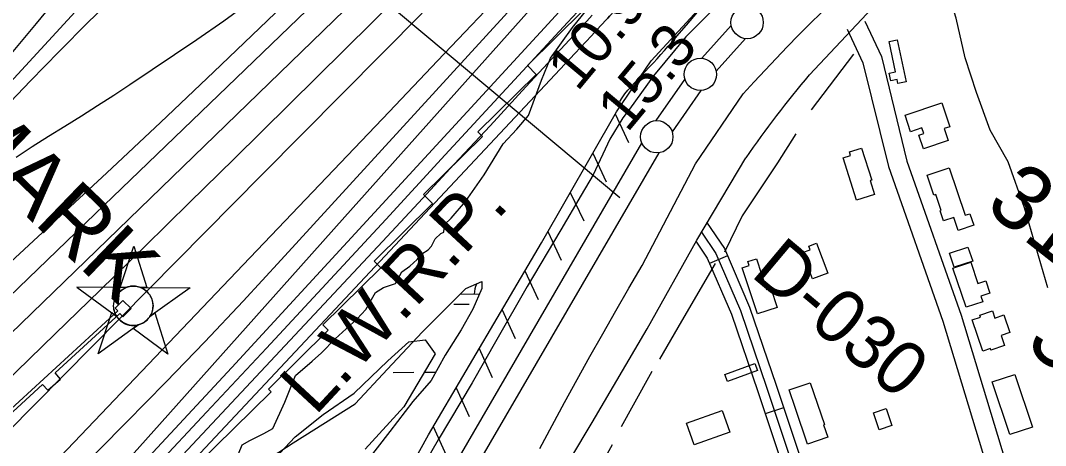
# Model space of a CAD drawing. Extents: x 3598634 to 3636690, y 517270 to 542944.
# Drawn here: x 3604825 to 3606411, y 525564 to 526222 of the extents above; entities that cross this region are included whole.
import ezdxf

# ---------------------------------------------------------------- set-up
doc = ezdxf.new("R2010")
doc.units = 0
for name, color, linetype in [('V-BLDG-OTLN', 7, 'Continuous'), ('V-CHAN-DOCK', 7, 'Continuous'), ('V-CHAN-NAID', 7, 'Continuous'), ('V-LEVE-TOET', 7, 'Continuous'), ('V-RIVR-EDGE', 7, 'Continuous'), ('V-RIVR-RANG', 7, 'Continuous'), ('V-RIVR-RANG-IDEN', 7, 'Continuous'), ('V-ROAD-CNTR', 7, 'Continuous'), ('V-RRAP-FSHR', 7, 'Continuous'), ('V-RRAP-RVMT', 7, 'Continuous'), ('V-SITE-VEGE', 7, 'Continuous'), ('V-SURV-IDEN', 7, 'Continuous'), ('V-SURV-LINE', 7, 'Continuous'), ('V-TOPO-DPTH', 7, 'Continuous'), ('V-TOPO-MAJR', 7, 'Continuous'), ('V-TOPO-MINR', 7, 'Continuous'), ('V-TOPO-SHOR', 7, 'Continuous'), ('V-TOPO-WATR', 7, 'Continuous'), ('V-TOPO-WATR-IDEN', 7, 'Continuous'), ('V-WETL-SWMP', 7, 'Continuous')]:
    doc.layers.add(name, color=color, linetype=linetype)

msp = doc.modelspace()

# ---------------------------------------------------------------- linework, layer by layer
at = {"layer": 'V-BLDG-OTLN'}
for points in [[(3606181.2, 526192), (3606195.4, 526126.8), (3606182.7, 526124), (3606181.3, 526130.3), (3606171.5, 526128.1), (3606168.9, 526140.2), (3606179, 526142.4), (3606168.8, 526189.3)], [(3606193.8, 526075.1), (3606250.7, 526094), (3606262.8, 526057.3), (3606254.4, 526054.5), (3606260.6, 526035.8), (3606222, 526023), (3606215, 526044.1), (3606222.6, 526046.7), (3606219.7, 526055.3), (3606202.3, 526049.5)], [(3606107.5, 526018.2), (3606126.1, 526024.2), (3606142, 525974.7), (3606139.6, 525973.9), (3606146.5, 525952.5), (3606118.7, 525943.7), (3606097.7, 526009.2), (3606109.2, 526012.9)], [(3606261.9, 525993.9), (3606286.8, 525920.3), (3606294, 525922.7), (3606300, 525904.8), (3606275.6, 525896.6), (3606268.9, 525916.7), (3606253.2, 525911.4), (3606248, 525926.9), (3606249.6, 525927.4), (3606241.2, 525952.3), (3606238.1, 525951.3), (3606227.7, 525982.4)], [(3606056.7, 525877), (3606074.2, 525830.8), (3606050.2, 525821.7), (3606034.8, 525862.4), (3606046.5, 525866.8), (3606044.5, 525872.3)], [(3606262.4, 525861.5), (3606291, 525871.1), (3606298.3, 525849.4), (3606269.7, 525839.8)], [(3605965.1, 525767.5), (3605941.6, 525838.8), (3605952.2, 525842.3), (3605950.2, 525848.6), (3605963.6, 525853), (3605979.2, 525805.5), (3605985.7, 525807.6), (3605995.6, 525777.5)], [(3606288.1, 525777.9), (3606267.8, 525838.5), (3606295.5, 525847.7), (3606306.5, 525814.8), (3606318.4, 525818.8), (3606324.8, 525799.8), (3606311, 525795.1), (3606313.9, 525786.5)], [(3606313.9, 525709.9), (3606297.3, 525758.3), (3606310.3, 525762.7), (3606309.3, 525765.7), (3606328.9, 525772.4), (3606332.7, 525761.1), (3606346.7, 525765.9), (3606356, 525738.7), (3606342.3, 525734), (3606347.5, 525718.7), (3606326.5, 525711.6), (3606325.7, 525713.9)], [(3605914.9, 525673.7), (3605961.1, 525690.7), (3605965.1, 525679.9), (3605918.6, 525663)], [(3606363.5, 525673.8), (3606390.7, 525592.3), (3606355.9, 525580.7), (3606328.7, 525662.2)], [(3606014.4, 525650), (3606047, 525661.1), (3606068.9, 525596.6), (3606067.6, 525596.1), (3606074.2, 525576.8), (3606042.5, 525566), (3606023.8, 525621.2), (3606024.1, 525621.3)], [(3605922.5, 525584.8), (3605867.1, 525565), (3605855.2, 525598.3), (3605910.6, 525618.1)], [(3606164.6, 525621.1), (3606173.4, 525595), (3606153.7, 525588.4), (3606145, 525614.5)]]:
    msp.add_lwpolyline(points, close=True, dxfattribs=at)
at = {"layer": 'V-CHAN-DOCK'}
msp.add_lwpolyline([(3604778.3, 525563.9), (3604766.7, 525574.4), (3604858.4, 525658.5), (3604866.7, 525649.7), (3604886.5, 525666.4), (3604878.2, 525676.6), (3604978.3, 525768.3), (3604983, 525762.9), (3604995.7, 525775.9), (3604982.7, 525788.5), (3604971.2, 525776.7), (3604975.1, 525772.1), (3604688.2, 525509.3)], dxfattribs=at)
at = {"layer": 'V-CHAN-NAID'}
for points in [[(3604988.3, 525808.6), (3604978.7, 525808.7), (3604999.8, 525872.2), (3605020.1, 525808.4), (3605010.5, 525808.5), (3605008.9, 525809.1), (3605006.8, 525809.7), (3605004.8, 525810.1), (3605002.7, 525810.4), (3605001.6, 525810.5), (3605000, 525810.6), (3604998.3, 525810.6), (3604996.9, 525810.6), (3604995, 525810.4), (3604993.7, 525810.1), (3604991.9, 525809.7), (3604990.4, 525809.3), (3604989.3, 525809)], [(3604988.3, 525808.6), (3604911.8, 525809.2), (3604973.4, 525763.8), (3604972.3, 525765.7), (3604971.5, 525767.3), (3604970.6, 525769.3), (3604969.9, 525771.3), (3604969.6, 525772.7), (3604969.2, 525774.3), (3604969, 525775.7), (3604968.8, 525777.3), (3604968.7, 525779.1), (3604968.7, 525780.6), (3604968.8, 525782.7), (3604968.9, 525784.3), (3604969.3, 525786.5), (3604969.8, 525788.5), (3604970.4, 525790.3), (3604971.1, 525792), (3604971.8, 525793.6), (3604972.6, 525795.1), (3604973.7, 525796.9), (3604974.7, 525798.4), (3604975.7, 525799.6), (3604976.7, 525800.8), (3604978, 525802.1), (3604979.1, 525803.1), (3604980.8, 525804.5), (3604982, 525805.3), (3604983.7, 525806.4), (3604985.4, 525807.4), (3604986.9, 525808)], [(3605010.5, 525808.5), (3605087, 525807.9), (3605024.8, 525763.4), (3605025.7, 525764.9), (3605026.7, 525766.7), (3605027.4, 525768.3), (3605028.1, 525770.3), (3605028.7, 525772.1), (3605029.1, 525773.7), (3605029.4, 525775.7), (3605029.6, 525777.3), (3605029.7, 525779.5), (3605029.7, 525781.6), (3605029.5, 525783.8), (3605029.2, 525785.5), (3605028.7, 525787.8), (3605028.1, 525789.9), (3605027.4, 525791.9), (3605026.7, 525793.3), (3605025.7, 525795.2), (3605024.6, 525797), (3605023.4, 525798.7), (3605022.2, 525800.2), (3605020.9, 525801.6), (3605019.3, 525803.1), (3605017.5, 525804.5), (3605015.8, 525805.7), (3605014, 525806.8), (3605012.5, 525807.6)], [(3605006.7, 525750.5), (3604944.5, 525706), (3604965.7, 525769.5), (3604973.4, 525763.8), (3604974, 525762.8), (3604975.4, 525760.9), (3604976.6, 525759.5), (3604978.1, 525758), (3604979.5, 525756.8), (3604980.9, 525755.6), (3604982.3, 525754.6), (3604984, 525753.6), (3604985.7, 525752.7), (3604987.5, 525751.9), (3604988.9, 525751.3), (3604990.6, 525750.8), (3604992.8, 525750.2), (3604994.3, 525749.9), (3604996.4, 525749.7), (3604997.9, 525749.6), (3604999.8, 525749.6), (3605001.4, 525749.6), (3605003.2, 525749.8), (3605005.1, 525750.1)], [(3605024.8, 525763.4), (3605032.6, 525769), (3605052.8, 525705.2), (3604998.9, 525744.9), (3605006.7, 525750.5), (3605008.4, 525751), (3605010, 525751.5), (3605012.2, 525752.5), (3605013.9, 525753.3), (3605015.8, 525754.4), (3605017.5, 525755.7), (3605019.1, 525756.9), (3605020.4, 525758.1), (3605021.7, 525759.5), (3605022.9, 525760.9), (3605024.1, 525762.4)]]:
    msp.add_lwpolyline(points, close=True, dxfattribs=at)
msp.add_circle((3604999.2, 525780.1), 30.5, dxfattribs=at)
at = {"layer": 'V-LEVE-TOET'}
for points in [[(3606412.9, 526771.3), (3606321, 526672.2), (3606244.2, 526591.9), (3606161, 526504.1), (3606078, 526420.6), (3606046.4, 526388.1), (3605974.7, 526314.2), (3605894.3, 526236.6), (3605854.3, 526196.6), (3605804.3, 526136), (3605767.1, 526084.7), (3605756.6, 526070.9), (3605736.9, 526037.9), (3605711.1, 525983), (3605692.4, 525951.1), (3605660.9, 525897.5), (3605608.7, 525809.9), (3605561.9, 525727.9), (3605523.4, 525661), (3605471.1, 525572.6), (3605425.5, 525493.5)], [(3605628.1, 525559.2), (3605647.2, 525595), (3605666.6, 525630.6), (3605686.1, 525666.2), (3605705.8, 525701.6), (3605725.8, 525736.9), (3605745.9, 525772.2), (3605766.1, 525807.3), (3605786.6, 525842.3), (3605869.4, 525999.7), (3605943.2, 526108), (3605960, 526126.5), (3605977, 526144.8), (3605994.1, 526163), (3606011.3, 526181), (3606028.8, 526198.9), (3606046.3, 526216.6), (3606064.1, 526234.1)]]:
    msp.add_lwpolyline(points, dxfattribs=at)
at = {"layer": 'V-RIVR-EDGE'}
for points in [[(3605415, 525832.5), (3605427.1, 525841.5), (3605438.5, 525851.6), (3605445.7, 525860.6), (3605455.3, 525866.6), (3605460.8, 525872.6), (3605466.2, 525884), (3605475.2, 525891.8), (3605480, 525894.2), (3605480.7, 525906.2), (3605490.9, 525915.7), (3605513.2, 525941.5), (3605542.1, 525982.9), (3605571.6, 526030.8), (3605592.7, 526053.6), (3605610.7, 526074.5), (3605630.7, 526129.1), (3605644.6, 526163.3), (3605678.9, 526210.6), (3605730.1, 526274.1)], [(3605162.2, 525551), (3605167.6, 525564.8), (3605179.7, 525571.9), (3605201.3, 525582.7), (3605215.1, 525590.4), (3605233.8, 525631.2), (3605250.2, 525672), (3605276, 525694.2), (3605290.5, 525707.3), (3605311.5, 525728.9), (3605345.8, 525760), (3605359.1, 525774.4), (3605374.1, 525800.8), (3605386.2, 525808.5), (3605404.8, 525814.5), (3605415, 525832.5)]]:
    msp.add_lwpolyline(points, dxfattribs=at)
at = {"layer": 'V-RIVR-RANG'}
msp.add_line((3605752.3, 525947.2), (3604907, 526654.1), dxfattribs=at)
at = {"layer": 'V-ROAD-CNTR'}
for p, q in [((3605918.7, 525857.7), (3605891.1, 525845.8)), ((3606005.7, 525622.2), (3605977.3, 525612.7))]:
    msp.add_line(p, q, dxfattribs=at)
for points in [[(3606045.5, 526137.4), (3606158.7, 526258.2), (3606346.2, 526448.4), (3606448.4, 526552.7)], [(3606131.4, 526220.8), (3606157, 526166), (3606196.6, 526004.2), (3606280.7, 525765.5), (3606348.6, 525540.7), (3606476.7, 525167.6), (3606584.2, 524859.8), (3606648.7, 524665.4), (3606725.5, 524430.1), (3606816.1, 524167.1), (3607097, 523321.9), (3607127.8, 523215.6)], [(3606104.2, 526208.1), (3606128.5, 526155.9), (3606167.8, 525995.6), (3606252.2, 525756.1), (3606320, 525531.5), (3606448.4, 525157.8), (3606555.8, 524850.1), (3606620.2, 524656), (3606697, 524420.5), (3606787.7, 524157.5), (3607068.3, 523312.9), (3607099, 523207.3)], [(3605516.1, 525279.6), (3605610.3, 525434.1), (3605709.5, 525599.5), (3605794.6, 525744.6), (3605871.2, 525881.6), (3605947.3, 526009.1)], [(3605886.3, 525909.4), (3605914, 525868.6), (3605953.1, 525778), (3605994.1, 525657.2), (3606083.4, 525389.7)], [(3605878.6, 525894.1), (3605900.8, 525861.3), (3605939, 525772.6), (3605979.8, 525652.4), (3606069.1, 525385)], [(3605869.8, 525880.4), (3605887.5, 525854.1), (3605925, 525767.2), (3605965.6, 525647.6), (3606054.9, 525380.2)]]:
    msp.add_lwpolyline(points, dxfattribs=at)
msp.add_arc((3607237.9, 525122.6), 1565.8, 139.6012, 145.5193, dxfattribs=at)
at = {"layer": 'V-RRAP-FSHR'}
for p, q in [((3605745, 526077.1), (3605765.8, 526033)), ((3605710.2, 526016.4), (3605731, 525972.2)), ((3605675.4, 525955.6), (3605696.2, 525911.5)), ((3605640.6, 525894.9), (3605661.4, 525850.7)), ((3605605.3, 525834.4), (3605625.6, 525790)), ((3605569.8, 525774.1), (3605590.1, 525729.7)), ((3605534.4, 525713.8), (3605554.6, 525669.3)), ((3605498.9, 525653.4), (3605519.1, 525609)), ((3605463.4, 525593.1), (3605483.6, 525548.7))]:
    msp.add_line(p, q, dxfattribs=at)
msp.add_lwpolyline([(3605375.2, 525433.8), (3605456, 525580.5), (3605630.7, 525877.6), (3605746.8, 526080.3), (3605800.6, 526159), (3605867.3, 526231.6), (3605948.4, 526309.6), (3606191.9, 526556.5), (3606564.8, 526949.6), (3606877.9, 527278.9), (3607054.8, 527479.5), (3607380.2, 527856.8), (3607669.2, 528199.4), (3608066.5, 528645), (3608475.6, 529114.7), (3608696.8, 529377), (3608831.9, 529536), (3608922.8, 529648.8), (3609014.7, 529727.8), (3609124.2, 529832), (3609276.1, 529976.3)], dxfattribs=at)
at = {"layer": 'V-RRAP-RVMT'}
for p, q in [((3605609.3, 526152), (3605696.6, 526238)), ((3605532.5, 526049.4), (3605622.7, 526138.3)), ((3605622.7, 526138.3), (3605609.3, 526152)), ((3605539.7, 526042.1), (3605532.5, 526049.4)), ((3605448.4, 525952.2), (3605539.7, 526042.1)), ((3605462.2, 525938.2), (3605448.4, 525952.2)), ((3605371.9, 525849.3), (3605462.2, 525938.2)), ((3605292.6, 525750.7), (3605382.2, 525838.8)), ((3605382.2, 525838.8), (3605371.9, 525849.3)), ((3605208.5, 525651.3), (3605300.9, 525742.2)), ((3605300.9, 525742.2), (3605292.6, 525750.7)), ((3605097.5, 525533.9), (3605212.6, 525647.1)), ((3605212.6, 525647.1), (3605208.5, 525651.3))]:
    msp.add_line(p, q, dxfattribs=at)
at = {"layer": 'V-SITE-VEGE'}
for points in [[(3606414.6, 525807.8), (3606378.3, 525931.7), (3606353, 526003.1), (3606325.3, 526052.2), (3606304.4, 526110.3), (3606286.7, 526163.8), (3606272.5, 526225.2), (3606261.5, 526262), (3606261.6, 526293.2), (3606276.2, 526328.8), (3606310.9, 526371), (3606420.5, 526474.2)], [(3605187.4, 525511), (3605249.4, 525577.2), (3605293.1, 525611.9), (3605341.2, 525644.7), (3605393.1, 525695.1), (3605425.4, 525724.1), (3605450.7, 525727.3), (3605466.4, 525705.7), (3605417.6, 525623.7), (3605358.1, 525558.1)]]:
    msp.add_lwpolyline(points, dxfattribs=at)
at = {"layer": 'V-SURV-LINE'}
for points in [[(3605878.9, 526163.2), (3605924.6, 526213.8)], [(3605946.9, 526193.7), (3605901.2, 526143)], [(3605808.5, 526066.7), (3605853, 526130.5)], [(3605877.6, 526113.3), (3605833.1, 526049.5)], [(3605478, 525502.1), (3605786.4, 526032)], [(3605812.3, 526016.9), (3605503.9, 525487)]]:
    msp.add_lwpolyline(points, dxfattribs=at)
for centre in [(3605949.2, 526218.5), (3605876.7, 526138.3), (3605809.4, 526041.7)]:
    msp.add_circle(centre, 25, dxfattribs=at)
at = {"layer": 'V-TOPO-DPTH'}
for points in [[(3606525.5, 527088.4), (3606200.6, 526699.9), (3606131.5, 526620.2), (3606060.4, 526542.3), (3605986.6, 526467), (3605911, 526393.4), (3605761.2, 526253.1), (3605759, 526251), (3605756.9, 526249), (3605754.7, 526246.9), (3605752.5, 526244.9), (3605750.4, 526242.8), (3605748.3, 526240.7), (3605746.2, 526238.5), (3605744.1, 526236.4), (3605736.2, 526228.2), (3605733.7, 526225.5), (3605731.2, 526222.8), (3605716.7, 526207.1), (3605708.2, 526198), (3605699.7, 526188.8), (3605691.2, 526179.7), (3605682.6, 526170.6), (3605002.5, 525445.1)], [(3604758.1, 525620), (3604878.3, 525736.7), (3604947.7, 525804.3), (3605017, 525872), (3605086.1, 525939.8), (3605155.1, 526007.8), (3605497.3, 526345.9)], [(3604758.1, 525620), (3604878.3, 525736.7), (3604947.7, 525804.3), (3605017, 525872), (3605086.1, 525939.8), (3605155.1, 526007.8), (3605497.3, 526345.9)], [(3604855.2, 525513.7), (3605169.3, 525843.3), (3605244.5, 525922.3), (3605319.7, 526001.3), (3605394.9, 526080.3), (3605470, 526159.3), (3605586, 526281.4)], [(3605586, 526281.4), (3605470, 526159.3), (3605394.9, 526080.3), (3605319.7, 526001.3), (3605244.5, 525922.3), (3605169.3, 525843.3), (3604855.2, 525513.7)], [(3605655.6, 526286.5), (3605326.7, 525918), (3605258.2, 525841.3), (3605189.7, 525764.5), (3605121.2, 525687.7), (3605052.7, 525610.9), (3604922.8, 525465.2)], [(3604922.8, 525465.2), (3605052.7, 525610.9), (3605121.2, 525687.7), (3605189.7, 525764.5), (3605258.2, 525841.3), (3605326.7, 525918), (3605655.6, 526286.5)], [(3605686.5, 526235.3), (3605671.2, 526218.7), (3605482, 526013.6), (3605389.9, 525913.8), (3605297.6, 525814.2), (3605205.1, 525714.7), (3605112.5, 525615.4), (3604952.5, 525444.2)], [(3604952.5, 525444.2), (3605112.5, 525615.4), (3605205.1, 525714.7), (3605297.6, 525814.2), (3605389.9, 525913.8), (3605482, 526013.6), (3605671.2, 526218.7), (3605686.5, 526235.3)], [(3604803.4, 525583.7), (3605198.6, 525983.2), (3605260.5, 526045.7), (3605322.4, 526108.1), (3605384.3, 526170.5), (3605446.3, 526232.8)], [(3605446.3, 526232.8), (3605384.3, 526170.5), (3605322.4, 526108.1), (3605260.5, 526045.7), (3605198.6, 525983.2), (3604803.4, 525583.7)]]:
    msp.add_lwpolyline(points, dxfattribs=at)
at = {"layer": 'V-TOPO-MAJR'}
for points in [[(3605519.2, 527085.7), (3605500.7, 527048.2), (3605480.6, 527011.4), (3605288.6, 526685.1), (3605269.7, 526654.7), (3605249.8, 526625), (3605228.4, 526596.3), (3605206.1, 526568.3), (3605180.6, 526537.9), (3605144.5, 526495.5), (3605108, 526453.4), (3605071, 526411.8), (3605033.5, 526370.6), (3604541.9, 525836.1), (3604531.7, 525824.9), (3604521.6, 525813.6), (3604511.7, 525802.2), (3604501.9, 525790.7), (3604418.3, 525691.8), (3604367.5, 525630.2), (3604317.7, 525567.9), (3604269.3, 525504.4)], [(3604758.4, 525688), (3605476.3, 526383.5)]]:
    msp.add_lwpolyline(points, dxfattribs=at)
at = {"layer": 'V-TOPO-MINR'}
for points in [[(3605002.5, 525445.1), (3605682.6, 526170.6), (3605691.2, 526179.7), (3605699.7, 526188.8), (3605708.2, 526198), (3605716.7, 526207.1), (3605731.2, 526222.8), (3605733.7, 526225.5), (3605736.2, 526228.2), (3605744.1, 526236.4), (3605746.2, 526238.5), (3605748.3, 526240.7), (3605750.4, 526242.8), (3605752.5, 526244.9), (3605754.7, 526246.9), (3605756.9, 526249), (3605759, 526251), (3605761.2, 526253.1), (3605911, 526393.4), (3605986.6, 526467), (3606060.4, 526542.3), (3606131.5, 526620.2), (3606200.6, 526699.9), (3606525.5, 527088.4)], [(3605752.3, 526096.1), (3605756, 526102.2), (3605760, 526108.2), (3605764.5, 526113.8), (3605769.2, 526119.2), (3605798.3, 526149.9), (3605804.1, 526156.2), (3605810, 526162.5), (3605815.7, 526168.9), (3605821.4, 526175.3), (3605827, 526181.7), (3605832.7, 526188.2), (3605838.3, 526194.7), (3605843.9, 526201.3), (3605855.3, 526214.7), (3605866.6, 526228), (3605877.9, 526241.2), (3605889.2, 526254.5), (3605900.6, 526267.7), (3606599.8, 527084.9)], [(3605009.4, 525531.5), (3605056.9, 525582.5), (3605104.4, 525633.6), (3605151.7, 525684.8), (3605199, 525736.1), (3605641.2, 526216.6), (3605663.6, 526240.8), (3605686, 526264.9), (3605708.5, 526288.8), (3605731.2, 526312.7), (3605839.1, 526426), (3605892.1, 526481.5), (3605945.1, 526537.1), (3605998.2, 526592.5), (3606051.3, 526648), (3606063.2, 526660.4), (3606110.3, 526709.7), (3606157.3, 526759.1), (3606204.1, 526808.6), (3606250.8, 526858.3), (3606297, 526908.3), (3606342.7, 526958.9), (3606387.4, 527010.3), (3606431.6, 527062.2)], [(3605247.7, 526750.2), (3605248.1, 526745.1), (3605247.3, 526739.7), (3605245.3, 526734.1), (3605243, 526728.7), (3605240.3, 526723.4), (3605237.4, 526718.2), (3605208.3, 526670.9), (3605205.9, 526667.2), (3605203.5, 526663.5), (3605200.9, 526660), (3605198.2, 526656.5), (3605011.6, 526418.4), (3604930.9, 526317.2), (3604849, 526216.9), (3604765.5, 526118.1), (3604680.9, 526020.1), (3604540.8, 525860.6), (3604525.5, 525843), (3604510.3, 525825.4), (3604495.2, 525807.6), (3604480.2, 525789.8), (3604361.5, 525647.7), (3604287.8, 525558.3)], [(3604807.2, 525794.2), (3604851.6, 525836.9), (3604895.9, 525879.6), (3604940.3, 525922.3), (3605431.3, 526395.5)], [(3604758.1, 525620), (3604878.3, 525736.7), (3604947.7, 525804.3), (3605017, 525872), (3605086.1, 525939.8), (3605155.1, 526007.8), (3605497.3, 526345.9)], [(3604688, 525735.9), (3604958, 525986.1), (3605041.2, 526063.9), (3605124, 526142), (3605206.1, 526220.9), (3605287.8, 526300.2)], [(3604855.2, 525513.7), (3605169.3, 525843.3), (3605244.5, 525922.3), (3605319.7, 526001.3), (3605394.9, 526080.3), (3605470, 526159.3), (3605586, 526281.4)], [(3604903.4, 525513.7), (3604988.7, 525599.8), (3605049.4, 525661.8), (3605109.6, 525724.3), (3605169, 525787.5), (3605227.9, 525851.2), (3605623.2, 526283.8)], [(3604922.8, 525465.2), (3605052.7, 525610.9), (3605121.2, 525687.7), (3605189.7, 525764.5), (3605258.2, 525841.3), (3605326.7, 525918), (3605655.6, 526286.5)], [(3604975.3, 526263.4), (3604929.4, 526219.1), (3604884.3, 526173.9), (3604839.8, 526128.2), (3604542.3, 525816.2)], [(3604817.7, 526010.2), (3604842.7, 526026.6), (3604867.9, 526042.6), (3604893.3, 526058.3), (3604918.7, 526074), (3604943.9, 526089.9), (3604969, 526106.2), (3604993.8, 526122.7), (3605097.7, 526192.5), (3605139, 526221.2), (3605179.7, 526250.6)], [(3604803.4, 525583.7), (3605198.6, 525983.2), (3605260.5, 526045.7), (3605322.4, 526108.1), (3605384.3, 526170.5), (3605446.3, 526232.8)], [(3604977.5, 525444.6), (3605384.6, 525879.7), (3605440.4, 525939.3), (3605496, 525999.1), (3605551.5, 526058.9), (3605606.9, 526118.8), (3605701.2, 526220.8), (3605709.5, 526229.7)]]:
    msp.add_lwpolyline(points, dxfattribs=at)
at = {"layer": 'V-TOPO-SHOR'}
for p, q in [((3606113.8, 526169.4), (3606048.5, 526083.3)), ((3605740.4, 525565), (3605680.1, 525457.9))]:
    msp.add_line(p, q, dxfattribs=at)
for points in [[(3606024.8, 526046.3), (3605996.1, 526001.4), (3605941.5, 525919.6), (3605914.2, 525863.3)], [(3605899.9, 525845.5), (3605847.4, 525756.5), (3605813.7, 525697.4)], [(3605801.5, 525678.2), (3605772.7, 525626.2), (3605754, 525592.8)]]:
    msp.add_lwpolyline(points, dxfattribs=at)
at = {"layer": 'V-TOPO-WATR'}
msp.add_lwpolyline([(3604952.5, 525444.2), (3605112.5, 525615.4), (3605205.1, 525714.7), (3605297.6, 525814.2), (3605389.9, 525913.8), (3605482, 526013.6), (3605671.2, 526218.7), (3605686.5, 526235.3)], dxfattribs=at)
at = {"layer": 'V-WETL-SWMP'}
for p, q in [((3605505, 525798.1), (3605535, 525798.4)), ((3605506.8, 525798.1), (3605506.8, 525799.8)), ((3605495, 525782.5), (3605519, 525782.8)), ((3605401.1, 525677), (3605433.1, 525677.3)), ((3605449.1, 525677.5), (3605467.7, 525677.6))]:
    msp.add_line(p, q, dxfattribs=at)
msp.add_lwpolyline([(3605202, 525539.3), (3605246.5, 525568), (3605342.7, 525628.6), (3605392.6, 525682.1), (3605446.1, 525739.1), (3605513.8, 525806.9), (3605538.8, 525817.6), (3605538.8, 525806.9), (3605524.5, 525774.8), (3605506.7, 525742.7), (3605481.8, 525703.5), (3605460.4, 525664.3), (3605431.8, 525632.2), (3605396.2, 525585.8), (3605360.5, 525539.5)], dxfattribs=at)
msp.add_arc((3605562.1, 525799.1), 35.2, 155.3005, 181.3052, dxfattribs=at)

# ---------------------------------------------------------------- texts
at = {"layer": 'V-CHAN-NAID'}
msp.add_text('ADM/GROWMARK ', height=100, rotation=316.027, dxfattribs=at).set_placement((3604148.8, 526578.8))
at = {"layer": 'V-RIVR-RANG'}
for s, p in [('10.9', (3605686.3, 526110.2)), ('15.3', (3605763.6, 526046.7))]:
    msp.add_text(s, height=67, rotation=50.2983, dxfattribs=at).set_placement(p)
at = {"layer": 'V-RIVR-RANG-IDEN'}
msp.add_text('D-030', height=83, rotation=319.9543, dxfattribs=at).set_placement((3605952.9, 525827.3))
at = {"layer": 'V-SURV-IDEN'}
for s, rotation, p in [('3140+56.9', 321.824, (3606314.8, 525930.9)), ('3139+48.7', 321.6093, (3606377.2, 525717.2))]:
    msp.add_text(s, height=100, rotation=rotation, dxfattribs=at).set_placement(p)
at = {"layer": 'V-TOPO-WATR-IDEN'}
msp.add_text('L.W.R.P.', height=83, rotation=47.1247, dxfattribs=at).set_placement((3605280.7, 525608.8))

doc.saveas('drawing.dxf')
